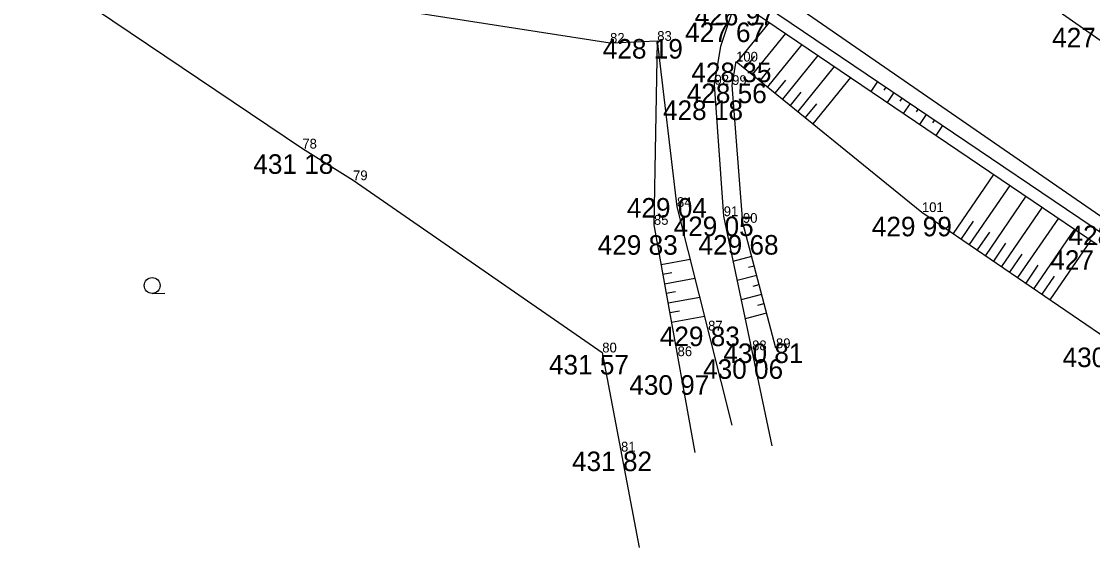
# Model space of a CAD drawing. Extents: x -559180 to -551373, y -1076947 to -1072071.
# Drawn here: x -554450 to -554395.3, y -1073771.9 to -1073744.9 of the extents above; entities that cross this region are included whole.
import ezdxf

# ---------------------------------------------------------------- set-up
doc = ezdxf.new("R2010")
doc.units = 0
for name, color, linetype in [('12_PLOTY', 7, 'Continuous'), ('17_KOMUNIKACE', 7, 'Continuous'), ('1_VODA_ZN', 7, 'Continuous'), ('26_SRAFY', 7, 'Continuous'), ('27_HRANA_PATA', 7, 'Continuous'), ('3_BODY', 7, 'Continuous'), ('45_ZN_KULTURY', 7, 'Continuous'), ('6_VYSKY', 7, 'Continuous')]:
    doc.layers.add(name, color=color, linetype=linetype)

# ---------------------------------------------------------------- blocks, each defined once
blk = doc.blocks.new('ZAHRAD')
at = {"layer": '45_ZN_KULTURY'}
blk.add_line((0, 0), (0.65, 0.003), dxfattribs=at)
blk.add_circle((0, 0.403), 0.403, dxfattribs=at)
blk = doc.blocks.new('POINT_DISPLAY')
blk.add_line((0, 0), (0, 0))

msp = doc.modelspace()

# ---------------------------------------------------------------- linework, layer by layer
at = {"layer": '12_PLOTY'}
for p, q in [((-554453.18, -1073739.63), (-554435.66, -1073751.45)), ((-554435.66, -1073751.45), (-554433.07, -1073753.07)), ((-554433.07, -1073753.07), (-554420.33, -1073761.88)), ((-554420.33, -1073761.88), (-554418.44, -1073771.862))]:
    msp.add_line(p, q, dxfattribs=at)
at = {"layer": '17_KOMUNIKACE'}
for p, q in [((-554400.73, -1073741.8), (-554387.17, -1073751.31)), ((-554412.12, -1073742.98), (-554394.12, -1073755.41)), ((-554435.08, -1073743.68), (-554419.93, -1073746.04)), ((-554419.93, -1073746.04), (-554417.52, -1073745.94)), ((-554417.52, -1073745.94), (-554416.51, -1073754.44)), ((-554414.12, -1073754.91), (-554414.59, -1073748.18)), ((-554416.51, -1073754.44), (-554413.701, -1073765.608)), ((-554411.636, -1073766.661), (-554414.12, -1073754.91))]:
    msp.add_line(p, q, dxfattribs=at)
msp.add_lwpolyline([(-554414.59, -1073748.18), (-554414.264, -1073746.216), (-554413.72, -1073744.58)], dxfattribs=at)
at = {"layer": '26_SRAFY'}
for p, q in [((-554411.795, -1073745.001), (-554413.445, -1073747.037)), ((-554410.964, -1073745.564), (-554412.668, -1073747.666)), ((-554410.133, -1073746.127), (-554411.891, -1073748.296)), ((-554412.553, -1073746.731), (-554413.056, -1073747.351)), ((-554409.302, -1073746.69), (-554411.114, -1073748.926)), ((-554411.76, -1073747.34), (-554412.28, -1073747.981)), ((-554408.471, -1073747.253), (-554410.337, -1073749.555)), ((-554410.967, -1073747.95), (-554411.503, -1073748.611)), ((-554407.64, -1073747.816), (-554409.561, -1073750.185)), ((-554406.579, -1073748.535), (-554406.235, -1073748.027)), ((-554410.174, -1073748.56), (-554410.726, -1073749.24)), ((-554405.924, -1073748.459), (-554405.821, -1073748.307)), ((-554405.751, -1073749.096), (-554405.407, -1073748.587)), ((-554409.381, -1073749.169), (-554409.949, -1073749.87)), ((-554405.096, -1073749.02), (-554404.993, -1073748.867)), ((-554404.923, -1073749.657), (-554404.578, -1073749.147)), ((-554404.268, -1073749.58), (-554404.164, -1073749.427)), ((-554404.095, -1073750.218), (-554403.75, -1073749.707)), ((-554403.439, -1073750.14), (-554403.336, -1073749.987)), ((-554403.267, -1073750.779), (-554402.922, -1073750.267)), ((-554400.328, -1073752.771), (-554402.396, -1073755.791)), ((-554399.5, -1073753.332), (-554401.571, -1073756.356)), ((-554398.672, -1073753.893), (-554400.746, -1073756.921)), ((-554397.844, -1073754.454), (-554399.921, -1073757.486)), ((-554401.363, -1073755.167), (-554401.984, -1073756.074)), ((-554397.016, -1073755.014), (-554399.096, -1073758.051)), ((-554400.537, -1073755.731), (-554401.159, -1073756.639)), ((-554396.188, -1073755.575), (-554398.271, -1073758.616)), ((-554395.36, -1073756.136), (-554397.446, -1073759.181)), ((-554399.711, -1073756.295), (-554400.333, -1073757.204)), ((-554415.834, -1073757.127), (-554417.322, -1073757.395)), ((-554413.634, -1073757.209), (-554412.689, -1073756.96)), ((-554398.885, -1073756.858), (-554399.508, -1073757.769)), ((-554416.777, -1073757.805), (-554417.233, -1073757.887)), ((-554413.427, -1073758.189), (-554412.434, -1073757.927)), ((-554412.852, -1073757.52), (-554412.562, -1073757.444)), ((-554398.059, -1073757.422), (-554398.683, -1073758.334)), ((-554415.59, -1073758.099), (-554417.145, -1073758.379)), ((-554412.612, -1073758.491), (-554412.307, -1073758.411)), ((-554397.233, -1073757.986), (-554397.858, -1073758.899)), ((-554416.579, -1073758.785), (-554417.056, -1073758.871)), ((-554413.22, -1073759.168), (-554412.179, -1073758.894)), ((-554415.345, -1073759.071), (-554416.967, -1073759.363)), ((-554412.371, -1073759.462), (-554412.052, -1073759.377)), ((-554416.382, -1073759.766), (-554416.879, -1073759.855)), ((-554415.101, -1073760.043), (-554416.79, -1073760.347)), ((-554413.013, -1073760.148), (-554411.924, -1073759.861))]:
    msp.add_line(p, q, dxfattribs=at)
at = {"layer": '27_HRANA_PATA'}
for p, q in [((-554412.9, -1073743.52), (-554394.65, -1073755.86)), ((-554413.08, -1073744.13), (-554395.03, -1073756.36)), ((-554417.52, -1073745.94), (-554417.69, -1073755.35)), ((-554413.69, -1073748.2), (-554413.49, -1073747)), ((-554413.49, -1073747), (-554403.99, -1073754.7)), ((-554413.14, -1073755.25), (-554413.69, -1073748.2)), ((-554403.99, -1073754.7), (-554394.22, -1073761.39)), ((-554417.69, -1073755.35), (-554415.594, -1073766.99)), ((-554411.45, -1073761.66), (-554413.14, -1073755.25))]:
    msp.add_line(p, q, dxfattribs=at)

# ---------------------------------------------------------------- block references
at = {"layer": '1_VODA_ZN'}
for p in [(-554419.93, -1073746.04), (-554417.52, -1073745.94), (-554413.49, -1073747), (-554414.59, -1073748.18), (-554413.69, -1073748.2), (-554435.66, -1073751.45), (-554433.07, -1073753.07), (-554416.51, -1073754.44), (-554414.12, -1073754.91), (-554403.99, -1073754.7), (-554417.69, -1073755.35), (-554413.14, -1073755.25), (-554414.92, -1073760.76), (-554411.45, -1073761.66), (-554420.33, -1073761.88), (-554416.48, -1073762.07), (-554412.67, -1073761.77), (-554419.37, -1073766.95)]:
    msp.add_blockref('POINT_DISPLAY', p, dxfattribs=at)
at = {"layer": '45_ZN_KULTURY'}
msp.add_blockref('ZAHRAD', (-554443.336, -1073758.859), dxfattribs=at)

# ---------------------------------------------------------------- texts
at = {"layer": '3_BODY'}
for s, p in [('82', (-554419.93, -1073746.04)), ('83', (-554417.52, -1073745.94)), ('100', (-554413.49, -1073747)), ('92', (-554414.59, -1073748.18)), ('99', (-554413.69, -1073748.2)), ('78', (-554435.66, -1073751.45)), ('79', (-554433.07, -1073753.07)), ('84', (-554416.51, -1073754.44)), ('91', (-554414.12, -1073754.91)), ('101', (-554403.99, -1073754.7)), ('85', (-554417.69, -1073755.35)), ('90', (-554413.14, -1073755.25)), ('87', (-554414.92, -1073760.76)), ('89', (-554411.45, -1073761.66)), ('80', (-554420.33, -1073761.88)), ('86', (-554416.48, -1073762.07)), ('88', (-554412.67, -1073761.77)), ('81', (-554419.37, -1073766.95))]:
    msp.add_text(s, height=0.5, dxfattribs=at).set_placement(p)
at = {"layer": '6_VYSKY'}
for s, p in [('426 97', (-554415.603, -1073745.148)), ('427 67', (-554416.096, -1073746.003)), ('427 90', (-554397.332, -1073746.273)), ('428 19', (-554420.3, -1073746.849)), ('428 35', (-554415.774, -1073748.055)), ('428 56', (-554416.011, -1073749.127)), ('428 18', (-554417.224, -1073749.988)), ('431 18', (-554438.165, -1073752.744)), ('429 04', (-554419.07, -1073754.981)), ('429 05', (-554416.68, -1073755.929)), ('429 99', (-554406.55, -1073755.939)), ('428 26', (-554396.497, -1073756.392)), ('429 83', (-554420.562, -1073756.883)), ('429 68', (-554415.407, -1073756.875)), ('427 64', (-554397.425, -1073757.654)), ('429 83', (-554417.388, -1073761.558)), ('430 81', (-554414.138, -1073762.421)), ('430 54', (-554396.799, -1073762.629)), ('431 57', (-554423.056, -1073763.008)), ('430 06', (-554415.175, -1073763.229)), ('430 97', (-554418.948, -1073764.043)), ('431 82', (-554421.875, -1073767.95))]:
    msp.add_text(s, height=1, dxfattribs=at).set_placement(p)

doc.saveas('drawing.dxf')
